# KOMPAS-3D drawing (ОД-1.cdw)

Referenced files in P:\Компас\: Общие данные ГСН.cdw
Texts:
  Перекладка газопровода низкого давления, проложенного   по пр. Карла Маркса, д. 480, 484, 486
  Морозов А.В.
  Текст на чертеже
  Размерные надписи
  Шероховатость
  Линия-выноска #1
  Линия-выноска #2
  Линия-выноска #3
  Отклонения формы и база
  Заголовок таблицы
  Ячейка таблицы
  Стрелка вида
  Обозначение изменения
  Фигурная скобка
  Номер узла
  Марка координационной оси
  VRCB
  Выносная надпись
  Обозначение узла
  Марка/позиционное обозначение с линией-выноской
  Марка/позиционное обозначение на линии
  Марка/позиционное обозначение без линии-выноски
  Body Text 2
  header
  Body Text
  Courier New
  Normal
  Материал-Предприятие
  Лит-Масса-Масштаб
  TXT
  txt
  Ведомоть прилагаемых документов
  Прилагаемые документы
  Спецификация оборудования, изделий и материалов
  Выход газопровода из земли
  Установка блокиратора на задвижке
  Ведомость основных комплектов рабочих чертежей
  Ведомоть рабочих четежей основного комплекта ГСН
  Общие данные (начало)
  Общие данные (окончание)
  Лист согласований
  План газопровода М 1:500. Узлы газопровода
  Профиль газопровода
  Гидравлический расчет
  Наружные газопроводы
  Смета на строительство
  Газопровод низкого давления
  Ситуационный план.
  нед.
  кер.400
  гл.2.6
  чуг.200
  гл. 1.8
  ст.100
  кер.200
  кер.300
  ул. Карла Маркса
  погреба
  ст.300
  гл.1.5
  пл.
  каб.
  ст.150
  в зем.
  ст.100 н.д.
  по стене
  ст.200
  ящ.
  гл.1.0
  кер.150
  кер.  200
  кер. 100
  асб.200
  не найд.
  RP1
  RP2
  ориент.
  асб.400
  Кр. линия
  м. врезки ПК0 (узел А)
  котлован 2х2х2
  выход из земли
  ПК0+16,5
  м. переврезки  (узел Б)
  Г1  159х4,5 (демонт.)
  CONTI_RGB_0_0_0_THICK_0.18
  CONTI_RGB_0_255_0_THICK_0.18
  POLYLINE_STYLE_0.09_RGB_168_80_0
  STROT_RGB_0_0_0_SC_1_THICK_0.18
  POLYLINE_STYLE_0.18_RGB_168_80_0
  POLYLINE_STYLE_0.30_RGB_168_80_0
  CONTI_RGB_128_64_0_THICK_0.18
  CONTI_RGB_0_0_255_THICK_0.18
  POLYLINE_STYLE_0.18_RGB_0_0_255
  CONTI_RGB_0_0_255_THICK_0.6
  POLYLINE_STYLE_0.18_RGB_0_0_0
  POLYLINE_STYLE_0.80_RGB_0_0_255
  POLYLINE_STYLE_0.70_RGB_0_0_0
  CONTI_RGB_0_0_255_THICK_0.5
  CONTI_RGB_0_0_0_THICK_0.7
  POLYLINE_STYLE_0.50_RGB_0_0_255
  POLYLINE_STYLE_0.24_RGB_168_80_0
  POLYLINE_STYLE_0.30_RGB_0_0_255
  Разраб
  ООО "Проект-Сервис"
  Пирюшев
  .Норм.контр.
  Котлова
  ГИП
  Перекладка газопровода низкого давления, проложенного
  по пр. Карла Маркса, д. 480, 484, 486
Dimensions and other numbers on the sheet: 1723-067-ГСН; 7; 1723-067-ГСН.С; 1723-067-ГСН.У1; 1723-067-ГСН.У2; 1; 2; 3; 4; 5; 6; 1723-067-СМ; 96; 96.95; 97.31; 96.41; 97.65; 97.02; 97.90; 97.21; 98.17; 95.61; 96.22; 97.59; 96.99; 97.88; 96.69; 96.52; 96.10; 97.32; 96.78; 97.10; 96.62; 97.82; 97.44; 97.91; 96.32; 95.69; 96.97; 97.58; 96.23; 96.86; 96.25; 96.47; 2кн; 12V; +3.2; +0.5; 480; 9пж; 94.15лот.; 95.53; 95.41; 98.43; 98.33; 96.14; 96.24; 97.33; 97.01; 96.91; 96.02; 95.92; 97.05; 97.15; 95.09; 97.29; 96.39; 97.37; 94.67лот; 98.21; 94.61лот; 97.22; 97.12; 96.03; 96.13; 97.20; 97.30; 95.65лот; 97.74; 95.49лот.; 96.66; 94.26лот; 95.03; 96.83; 96.88; 94.68лот.; 94.54; 95.19; 96.45; 94.53; 96.33; 95.43; 96.44; 93.04лот.; 96.01; 94.51лот; 96.65; 98.11; 103.31каб.; 95.90; 104.45в.оп.; 97.56; 97.06; 98.05; 96.46; 96.31; 94.83; 96.73; 95.93; 98; 10кВ; 472б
